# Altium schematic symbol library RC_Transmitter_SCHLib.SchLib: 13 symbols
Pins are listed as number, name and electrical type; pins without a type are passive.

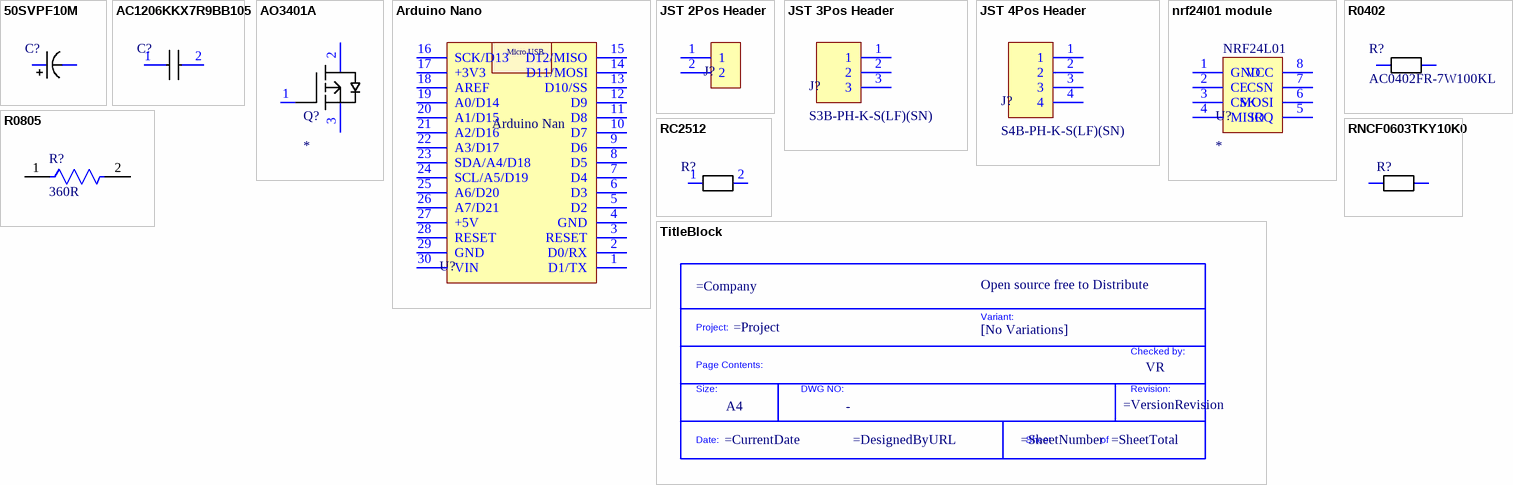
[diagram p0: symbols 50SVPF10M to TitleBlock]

## 50SVPF10M
designator C?  (value not drawn)
CAP ALUM POLY 10UF 20% 50V SMD; Manufacturer: Panasonic; Manufacturer Part Number: 50SVPF10M; Description: Cap Aluminum Polymer 10uF 50VDC 20%( 6.3 X 5.9mm) SMD 0.04 Ohm 2500mA 5000h 105C T/R; ESR (Equivalent Series Resistance): 40mR; Ripple Current: 2.5A; Leakage Current: 100uA; Life (Hours): 5000Hour; Dissipation Factor: 12%
footprint Cap Poly SVPF
pins: 1 +, 2 -

## AC1206KKX7R9BB105
designator C?  (value not drawn)
CAP CER 1UF 50V X7R 1206; Manufacturer: Yageo; Manufacturer Part Number: AC1206KKX7R9BB105
footprint C1206 Yageo
pins: 1, 2

## AO3401A
designator Q?
Trans Mosfet P-ch 30V 4A 3-PIN SOT-23 T/r; Manufacturer: Alpha & Omega Semiconductor; Manufacturer Part Number: AO3401A; Rds On Max: 44mR; Input Capacitance: 1.2nF; Max Power Dissipation: 1.4W; Number of Elements: 1
footprint SOT23-3 (2N7002ET1G)
pins: 1 S, 2 D, 3 S

## Arduino Nano
designator U?  (value not drawn)
Arduino Nano Module
footprint Arduino nano
pins: 1 D1/TX, 2 D0/RX, 3 RESET, 4 GND, 5 D2, 6 D3, 7 D4, 8 D5, 9 D6, 10 D7, 11 D8, 12 D9, 13 D10/SS, 14 D11/MOSI, 15 D12/MISO, 16 SCK/D13, 17 +3V3, 18 AREF, 19 A0/D14, 20 A1/D15, 21 A2/D16, 22 A3/D17, 23 SDA/A4/D18, 24 SCL/A5/D19, 25 A6/D20, 26 A7/D21, 27 +5V, 28 RESET, 29 GND, 30 VIN

## JST 2Pos Header
designator J?, comment S2B-PH-K-S(LF)(SN)  (value not drawn)
Connector Header Through Hole, Right Angle 2 position 0.079" (2.00mm); Manufacturer: JST; Current Rating: 2A; Contact Resistance: 20mR; Voltage Rating: 100V; Number of Positions: 2; Gender: Male; Connector Type: Male Pin; Insulation Resistance: 1GR; Pitch: 2mm
footprint HDR 2POS JST
pins: 1, 2

## JST 3Pos Header
designator J?, comment S3B-PH-K-S(LF)(SN)
Connector Header Through Hole, Right Angle 3 position 0.079" (2.00mm); Manufacturer: JST
footprint HDR 3Pos JST
pins: 1, 2, 3

## JST 4Pos Header
designator J?, comment S4B-PH-K-S(LF)(SN)
Connector Header Through Hole, Right Angle 4 position 0.079" (2.00mm); Manufacturer: JST; Voltage Rating: 100V; Number of Poles: 4; Contact Resistance: 10mR; Current Rating: 2A; Insulation Resistance: 1GR; Gender: Male; Connector Type: Male Pin; Pitch: 2mm
footprint HDR 4POS JST
pins: 1, 2, 3, 4

## nrf24l01 module
designator U?
nrf24l01 module. 2.4Ghz Transmitter
footprint nrf24l01
pins: 1 GND, 2 CE, 3 CSK, 4 MISO, 5 IRQ, 6 MOSI, 7 CSN, 8 VCC

## R0402
designator R?, comment AC0402FR-7W100KL
100 kOhms ±1% 0.125W, 1/8W Chip Resistor 0402 (1005 Metric) Automotive AEC-Q200 Thick Film; Manufacturer: Yageo
footprint R0402 YAGEO
pins: 1, 2

## R0805
designator R?, comment 360R
RES SMD 360 OHM 1% 1/8W 0805AC0805FR-07360RL; Manufacturer: Yageo; Voltage Rating: 150V; Resistance: 360Ω; Tolerance: 0.01; Automotive Grade: Grade 0; Value: 360Ω
footprint FP-AC0805-MFG
footprint FP-AC0805-IPC_C
footprint FP-AC0805-IPC_B
footprint FP-AC0805-IPC_A
footprint R0805
pins: 1, 2

## RC2512
designator R?  (value not drawn)
220 Ohms ±5% 1W Chip Resistor 2512 (6432 Metric) Moisture Resistant Thick Film; Manufacturer: Yageo; Manufacturer Part Number: RC2512JK-07220RL; Resistance: 220R; Voltage Rating: 200V; Temperature Coefficient: 100ppm/°C
footprint R2512 YAGEO
pins: 1, 2

## RNCF0603TKY10K0
designator R?, comment 10KOhm Resistor  (value not drawn)
Res Thin Film 0603 10K Ohm 0.01% 0.1W(1/10W) ±5ppm/C Pad SMD Automotive T/R; Manufacturer: Stackpole Electronics; Manufacturer Part Number: RNCF0603TKY10K0; Resistance: 10kR; Max Power Dissipation: 100mW; Temperature Coefficient: 5ppm/°C
footprint RNCF0603
pins: 1, 2

## TitleBlock
designator *  Size: A4  Checked by: VR  (hidden comment: *)  (graphical)
Standard Title Block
